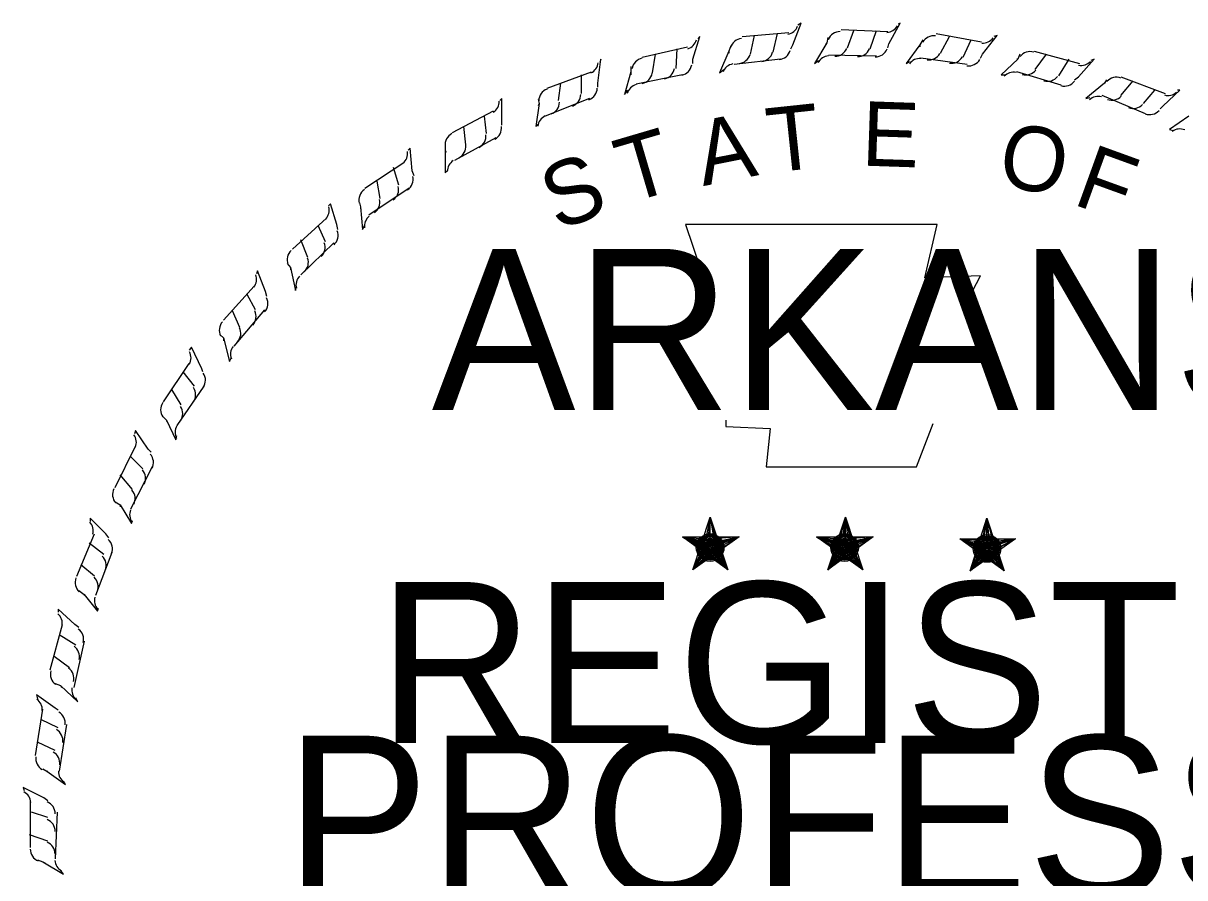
# Model space of a CAD drawing. Extents: x 1369528 to 1373075, y 373809 to 376031.
# Drawn here: x 1372616.5 to 1372751.6, y 374052.1 to 374151.6 of the extents above; entities that cross this region are included whole.
import ezdxf

# ---------------------------------------------------------------- set-up
doc = ezdxf.new("R2010")
doc.units = 0
doc.layers.add('R_Border Notes', color=7, linetype='Continuous')

msp = doc.modelspace()

# ---------------------------------------------------------------- linework, layer by layer
at = {"layer": 'R_Border Notes'}
for p, q in [((1372706.03, 374149.04), (1372706.99, 374151.56)), ((1372706.99, 374151.56), (1372706.63, 374151.32)), ((1372717.19, 374149.16), (1372718.51, 374151.56)), ((1372718.51, 374151.56), (1372718.27, 374151.44)), ((1372700.15, 374150), (1372705.55, 374150.48)), ((1372701.11, 374147.96), (1372701.59, 374150.12)), ((1372703.75, 374148.2), (1372704.23, 374150.36)), ((1372711.67, 374150.84), (1372717.07, 374150.6)), ((1372712.39, 374148.68), (1372713.11, 374150.72)), ((1372715.03, 374148.56), (1372715.75, 374150.72)), ((1372722.71, 374150.36), (1372727.99, 374149.4)), ((1372728.11, 374147.96), (1372729.79, 374150.12)), ((1372729.79, 374150.12), (1372729.43, 374150)), ((1372688.51, 374147.6), (1372693.79, 374148.8)), ((1372694.39, 374147.36), (1372695.23, 374150)), ((1372695.23, 374150), (1372694.99, 374149.76)), ((1372698.83, 374148.92), (1372698.59, 374148.32)), ((1372705.79, 374148.56), (1372706.03, 374149.04)), ((1372709.99, 374149.28), (1372708.55, 374146.88)), ((1372709.99, 374149.28), (1372709.87, 374149.16)), ((1372710.11, 374149.88), (1372709.99, 374149.28)), ((1372717.07, 374148.68), (1372717.19, 374149.16)), ((1372720.79, 374149.04), (1372719.23, 374146.88)), ((1372721.15, 374149.64), (1372720.79, 374149.04)), ((1372720.79, 374149.04), (1372720.79, 374148.8)), ((1372723.19, 374148.08), (1372724.27, 374150)), ((1372725.83, 374147.6), (1372726.79, 374149.64)), ((1372683.35, 374144.6), (1372683.71, 374147.36)), ((1372683.71, 374147.36), (1372683.59, 374147)), ((1372689.71, 374145.8), (1372690.07, 374147.96)), ((1372692.47, 374146.28), (1372692.59, 374148.56)), ((1372694.39, 374146.88), (1372694.39, 374147.36)), ((1372698.59, 374148.32), (1372697.51, 374145.8)), ((1372698.59, 374148.32), (1372698.59, 374148.08)), ((1372704.59, 374147.36), (1372699.19, 374146.76)), ((1372715.75, 374147.72), (1372710.23, 374147.84)), ((1372726.31, 374146.76), (1372720.91, 374147.48)), ((1372727.87, 374147.48), (1372728.11, 374147.96)), ((1372732.19, 374147.36), (1372730.27, 374145.56)), ((1372732.19, 374147.36), (1372732.07, 374147.36)), ((1372732.43, 374147.96), (1372732.19, 374147.36)), ((1372734.11, 374148.32), (1372739.39, 374146.88)), ((1372734.23, 374146.16), (1372735.55, 374147.96)), ((1372736.99, 374145.44), (1372738.19, 374147.36)), ((1372739.27, 374145.32), (1372741.07, 374147.36)), ((1372741.07, 374147.36), (1372740.71, 374147.24)), ((1372687.19, 374146.52), (1372687.19, 374145.92)), ((1372697.51, 374145.8), (1372697.99, 374146.16)), ((1372708.55, 374146.88), (1372709.03, 374147.24)), ((1372719.23, 374146.88), (1372719.59, 374147.12)), ((1372677.47, 374144), (1372682.63, 374145.92)), ((1372681.43, 374143.4), (1372681.43, 374145.56)), ((1372687.19, 374145.92), (1372686.47, 374143.28)), ((1372687.19, 374145.92), (1372687.19, 374145.56)), ((1372693.19, 374145.56), (1372687.79, 374144.48)), ((1372730.27, 374145.56), (1372730.75, 374145.56)), ((1372737.23, 374144.36), (1372732.07, 374145.92)), ((1372738.79, 374144.96), (1372739.27, 374145.32)), ((1372742.51, 374144.96), (1372742.27, 374144.6)), ((1372744.19, 374145.32), (1372749.35, 374143.4)), ((1372744.19, 374143.16), (1372745.63, 374144.84)), ((1372678.79, 374142.56), (1372679.03, 374144.6)), ((1372683.35, 374144.12), (1372683.35, 374144.6)), ((1372686.47, 374143.28), (1372686.83, 374143.76)), ((1372742.27, 374144.6), (1372740.11, 374142.8)), ((1372742.27, 374144.6), (1372742.03, 374144.36)), ((1372746.83, 374142.2), (1372748.15, 374143.76)), ((1372749.11, 374141.96), (1372751.03, 374143.76)), ((1372751.03, 374143.76), (1372750.79, 374143.76)), ((1372672.19, 374142.8), (1372671.95, 374142.56)), ((1372672.19, 374140.16), (1372672.19, 374142.8)), ((1372676.51, 374142.2), (1372676.15, 374139.56)), ((1372676.39, 374142.68), (1372676.51, 374142.2)), ((1372676.51, 374142.2), (1372676.39, 374141.96)), ((1372682.39, 374142.8), (1372677.23, 374140.76)), ((1372740.11, 374142.8), (1372740.59, 374142.92)), ((1372747.07, 374141), (1372742.03, 374143.16)), ((1372748.75, 374141.6), (1372749.11, 374141.96)), ((1372666.43, 374138.84), (1372671.23, 374141.36)), ((1372670.39, 374138.72), (1372670.15, 374140.76)), ((1372752.11, 374140.76), (1372749.83, 374139.2)), ((1372667.99, 374137.4), (1372667.75, 374139.56)), ((1372672.19, 374139.68), (1372672.19, 374140.16)), ((1372676.15, 374139.56), (1372676.39, 374139.8)), ((1372671.47, 374138.24), (1372666.67, 374135.6)), ((1372749.83, 374139.2), (1372750.31, 374139.08)), ((1372661.51, 374137.04), (1372661.27, 374136.8)), ((1372661.75, 374134.4), (1372661.51, 374137.04)), ((1372665.59, 374137.4), (1372665.59, 374136.8)), ((1372665.59, 374136.8), (1372665.59, 374134.16)), ((1372665.59, 374136.8), (1372665.71, 374136.56)), ((1372656.23, 374132.36), (1372660.79, 374135.36)), ((1372660.19, 374132.72), (1372659.59, 374134.76)), ((1372661.99, 374133.8), (1372661.75, 374134.4)), ((1372665.59, 374134.16), (1372665.83, 374134.4)), ((1372658.03, 374131.16), (1372657.67, 374133.2)), ((1372661.39, 374132.36), (1372656.71, 374129.24)), ((1372652.27, 374130.56), (1372652.03, 374130.32)), ((1372652.99, 374128.16), (1372652.27, 374130.56)), ((1372655.63, 374130.68), (1372655.75, 374130.2)), ((1372655.75, 374130.2), (1372655.99, 374127.56)), ((1372655.75, 374130.2), (1372655.75, 374129.96)), ((1372647.83, 374125.28), (1372651.79, 374128.88)), ((1372651.67, 374126.12), (1372650.83, 374128.04)), ((1372653.11, 374127.56), (1372652.99, 374128.16)), ((1372655.99, 374127.56), (1372656.23, 374128.04)), ((1372649.63, 374124.32), (1372648.79, 374126.36)), ((1372652.63, 374126), (1372648.79, 374122.28)), ((1372647.23, 374123.6), (1372647.59, 374123.12)), ((1372647.59, 374123.12), (1372648.19, 374120.48)), ((1372647.59, 374123.12), (1372647.59, 374122.88)), ((1372643.75, 374122.76), (1372643.63, 374122.4)), ((1372644.71, 374120.36), (1372643.75, 374122.76)), ((1372639.79, 374117), (1372643.39, 374120.96)), ((1372644.83, 374119.76), (1372644.71, 374120.36)), ((1372648.19, 374120.48), (1372648.31, 374120.96)), ((1372643.51, 374118.2), (1372642.55, 374120)), ((1372641.71, 374116.16), (1372640.87, 374118.08)), ((1372644.59, 374118.2), (1372640.99, 374114)), ((1372639.43, 374115.32), (1372639.79, 374114.96)), ((1372639.79, 374114.96), (1372640.51, 374112.2)), ((1372639.79, 374114.96), (1372639.79, 374114.6)), ((1372636.07, 374113.88), (1372635.83, 374113.52)), ((1372637.27, 374111.36), (1372636.07, 374113.88)), ((1372640.51, 374112.2), (1372640.75, 374112.68)), ((1372632.83, 374107.52), (1372635.83, 374111.96)), ((1372636.43, 374109.32), (1372635.11, 374111)), ((1372637.39, 374111), (1372637.27, 374111.36)), ((1372634.87, 374107.16), (1372633.79, 374108.96)), ((1372637.51, 374109.32), (1372634.39, 374104.76)), ((1372632.71, 374105.84), (1372633.19, 374105.36)), ((1372629.59, 374104.16), (1372629.47, 374103.8)), ((1372631.03, 374102), (1372629.59, 374104.16)), ((1372633.19, 374105.36), (1372634.27, 374103.08)), ((1372633.19, 374105.36), (1372633.19, 374105.24)), ((1372634.27, 374103.08), (1372634.39, 374103.56)), ((1372627.19, 374097.56), (1372629.59, 374102.36)), ((1372631.39, 374101.64), (1372631.03, 374102)), ((1372630.43, 374099.72), (1372628.99, 374101.16)), ((1372629.23, 374097.32), (1372627.79, 374099)), ((1372631.51, 374099.96), (1372628.99, 374095.04)), ((1372627.19, 374095.88), (1372627.79, 374095.52)), ((1372627.79, 374095.52), (1372629.11, 374093.36)), ((1372627.79, 374095.52), (1372627.79, 374095.28)), ((1372626.11, 374092.16), (1372624.31, 374093.96)), ((1372624.31, 374093.96), (1372624.31, 374093.6)), ((1372629.11, 374093.36), (1372629.23, 374093.72)), ((1372696.43, 374094.08), (1372695.95, 374091.8)), ((1372696.43, 374094.08), (1372696.19, 374091.8)), ((1372696.43, 374094.08), (1372696.31, 374091.8)), ((1372696.43, 374090.72), (1372696.43, 374094.08)), ((1372696.43, 374094.08), (1372697.03, 374091.8)), ((1372696.43, 374094.08), (1372696.91, 374091.8)), ((1372696.43, 374094.08), (1372696.79, 374091.8)), ((1372712.15, 374094.08), (1372711.55, 374091.8)), ((1372712.15, 374094.08), (1372711.79, 374091.8)), ((1372712.15, 374094.08), (1372711.91, 374091.8)), ((1372712.15, 374090.72), (1372712.15, 374094.08)), ((1372712.15, 374094.08), (1372712.75, 374091.8)), ((1372712.15, 374094.08), (1372712.63, 374091.8)), ((1372712.15, 374094.08), (1372712.39, 374091.8)), ((1372728.59, 374093.96), (1372728.11, 374091.68)), ((1372728.59, 374093.96), (1372728.23, 374091.68)), ((1372728.59, 374090.6), (1372728.59, 374093.96)), ((1372728.59, 374093.96), (1372729.31, 374091.68)), ((1372728.59, 374093.96), (1372729.19, 374091.68)), ((1372728.59, 374093.96), (1372728.83, 374091.68)), ((1372728.59, 374093.96), (1372728.59, 374091.68)), ((1372622.75, 374087.24), (1372624.79, 374092.16)), ((1372626.47, 374091.68), (1372626.11, 374092.16)), ((1372625.87, 374089.76), (1372624.19, 374091.08)), ((1372693.19, 374091.8), (1372696.43, 374090.72)), ((1372693.19, 374091.8), (1372695.59, 374091.56)), ((1372693.19, 374091.8), (1372695.59, 374091.32)), ((1372693.19, 374091.8), (1372695.59, 374091.2)), ((1372693.19, 374091.8), (1372695.47, 374090.84)), ((1372693.19, 374091.8), (1372695.47, 374090.6)), ((1372693.19, 374091.8), (1372695.47, 374090.36)), ((1372694.39, 374087.96), (1372696.43, 374090.72)), ((1372699.79, 374091.8), (1372696.43, 374090.72)), ((1372698.47, 374087.96), (1372696.43, 374090.72)), ((1372699.79, 374091.8), (1372696.79, 374091.56)), ((1372699.79, 374091.8), (1372697.03, 374091.2)), ((1372699.79, 374091.8), (1372697.03, 374091.08)), ((1372698.47, 374087.96), (1372697.15, 374090.6)), ((1372698.47, 374087.96), (1372697.39, 374090.6)), ((1372699.79, 374091.8), (1372697.63, 374090.96)), ((1372699.79, 374091.8), (1372697.87, 374090.84)), ((1372699.79, 374091.8), (1372697.99, 374090.6)), ((1372708.79, 374091.8), (1372712.15, 374090.72)), ((1372708.79, 374091.8), (1372711.19, 374091.56)), ((1372708.79, 374091.8), (1372711.19, 374091.32)), ((1372708.79, 374091.8), (1372711.19, 374091.2)), ((1372708.79, 374091.8), (1372711.19, 374090.84)), ((1372708.79, 374091.8), (1372711.07, 374090.6)), ((1372708.79, 374091.8), (1372711.07, 374090.36)), ((1372710.11, 374087.96), (1372712.15, 374090.72)), ((1372715.39, 374091.8), (1372712.15, 374090.72)), ((1372714.19, 374087.96), (1372712.15, 374090.72)), ((1372715.39, 374091.8), (1372712.51, 374091.56)), ((1372715.39, 374091.8), (1372712.63, 374091.2)), ((1372715.39, 374091.8), (1372712.63, 374091.08)), ((1372714.19, 374087.96), (1372712.87, 374090.6)), ((1372714.19, 374087.96), (1372712.99, 374090.6)), ((1372715.39, 374091.8), (1372713.23, 374090.96)), ((1372715.39, 374091.8), (1372713.47, 374090.84)), ((1372715.39, 374091.8), (1372713.59, 374090.6)), ((1372725.47, 374091.56), (1372728.59, 374090.6)), ((1372725.47, 374091.56), (1372727.87, 374091.44)), ((1372725.47, 374091.56), (1372727.87, 374091.2)), ((1372725.47, 374091.56), (1372727.63, 374090.96)), ((1372725.47, 374091.56), (1372727.63, 374090.72)), ((1372725.47, 374091.56), (1372727.63, 374090.48)), ((1372725.47, 374091.56), (1372727.63, 374090.36)), ((1372726.67, 374087.84), (1372728.59, 374090.6)), ((1372731.95, 374091.56), (1372728.59, 374090.6)), ((1372730.63, 374087.84), (1372728.59, 374090.6)), ((1372731.95, 374091.56), (1372729.07, 374091.44)), ((1372731.95, 374091.56), (1372729.19, 374091.2)), ((1372731.95, 374091.56), (1372729.19, 374090.96)), ((1372730.63, 374087.84), (1372729.67, 374090.6)), ((1372731.95, 374091.56), (1372729.79, 374090.84)), ((1372731.95, 374091.56), (1372730.03, 374090.6)), ((1372731.95, 374091.56), (1372730.15, 374090.6)), ((1372626.83, 374090), (1372624.91, 374084.96)), ((1372694.39, 374087.96), (1372695.59, 374090.48)), ((1372694.39, 374087.96), (1372695.59, 374090.24)), ((1372694.39, 374087.96), (1372695.83, 374090.12)), ((1372694.39, 374087.96), (1372696.43, 374090)), ((1372694.39, 374087.96), (1372696.19, 374089.88)), ((1372694.39, 374087.96), (1372696.43, 374089.76)), ((1372698.47, 374087.96), (1372696.43, 374089.88)), ((1372698.47, 374087.96), (1372696.43, 374089.76)), ((1372698.47, 374087.96), (1372696.79, 374089.88)), ((1372698.47, 374087.96), (1372697.03, 374090.24)), ((1372710.11, 374087.96), (1372711.19, 374090.48)), ((1372710.11, 374087.96), (1372711.19, 374090.24)), ((1372710.11, 374087.96), (1372711.43, 374090.12)), ((1372710.11, 374087.96), (1372712.03, 374090)), ((1372710.11, 374087.96), (1372711.79, 374089.88)), ((1372710.11, 374087.96), (1372712.15, 374089.76)), ((1372714.19, 374087.96), (1372712.03, 374089.88)), ((1372714.19, 374087.96), (1372712.03, 374089.76)), ((1372714.19, 374087.96), (1372712.39, 374089.88)), ((1372714.19, 374087.96), (1372712.75, 374090.24)), ((1372726.67, 374087.84), (1372727.63, 374090.36)), ((1372726.67, 374087.84), (1372727.87, 374090.12)), ((1372726.67, 374087.84), (1372727.99, 374090)), ((1372726.67, 374087.84), (1372728.23, 374089.76)), ((1372726.67, 374087.84), (1372728.59, 374089.76)), ((1372726.67, 374087.84), (1372728.71, 374089.64)), ((1372730.63, 374087.84), (1372728.59, 374089.76)), ((1372730.63, 374087.84), (1372728.59, 374089.52)), ((1372730.63, 374087.84), (1372729.07, 374089.76)), ((1372730.63, 374087.84), (1372729.31, 374090.12)), ((1372730.63, 374087.84), (1372729.43, 374090.48)), ((1372624.79, 374087.24), (1372623.23, 374088.56)), ((1372622.99, 374085.56), (1372623.59, 374085.08)), ((1372623.59, 374085.08), (1372625.15, 374083.16)), ((1372623.59, 374085.08), (1372623.59, 374084.96)), ((1372622.51, 374081.6), (1372620.59, 374083.4)), ((1372620.59, 374083.4), (1372620.59, 374083.04)), ((1372625.15, 374083.16), (1372625.27, 374083.52)), ((1372619.63, 374076.32), (1372621.07, 374081.6)), ((1372622.99, 374081.24), (1372622.51, 374081.6)), ((1372622.63, 374079.2), (1372620.71, 374080.4)), ((1372623.59, 374079.68), (1372622.39, 374074.28)), ((1372621.91, 374076.56), (1372620.11, 374077.88)), ((1372620.23, 374074.76), (1372620.83, 374074.52)), ((1372620.83, 374074.52), (1372622.87, 374072.6)), ((1372620.83, 374074.52), (1372620.95, 374074.28)), ((1372620.23, 374071.88), (1372618.07, 374073.44)), ((1372618.07, 374073.44), (1372618.19, 374072.96)), ((1372622.87, 374072.6), (1372622.63, 374073.08)), ((1372617.95, 374066.36), (1372618.79, 374071.76)), ((1372620.59, 374071.64), (1372620.23, 374071.88)), ((1372620.59, 374069.6), (1372618.55, 374070.56)), ((1372621.55, 374069.96), (1372620.71, 374064.56)), ((1372620.23, 374066.96), (1372618.19, 374067.92)), ((1372618.79, 374064.8), (1372619.27, 374064.56)), ((1372619.27, 374064.56), (1372621.43, 374063)), ((1372619.27, 374064.56), (1372619.39, 374064.56)), ((1372618.91, 374061.44), (1372616.51, 374062.64)), ((1372616.51, 374062.64), (1372616.63, 374062.28)), ((1372621.43, 374063), (1372621.19, 374063.36)), ((1372617.35, 374055.68), (1372617.35, 374061.08)), ((1372619.39, 374061.08), (1372618.91, 374061.44)), ((1372619.39, 374059.16), (1372617.47, 374059.76)), ((1372620.47, 374059.76), (1372620.23, 374054.36)), ((1372619.39, 374056.4), (1372617.23, 374057.12)), ((1372618.19, 374054.24), (1372618.79, 374054)), ((1372618.79, 374054), (1372621.19, 374052.56)), ((1372618.79, 374054), (1372619.03, 374053.88)), ((1372621.19, 374052.56), (1372620.83, 374053.04))]:
    msp.add_line(p, q, dxfattribs=at)
for points in [[(1372693.55, 374128.16), (1372696.19, 374120.36)], [(1372726.43, 374119.4), (1372727.87, 374122.16), (1372721.39, 374121.92), (1372722.83, 374128.16), (1372693.55, 374128.16)], [(1372698.23, 374105.36), (1372698.23, 374104.64), (1372703.39, 374104.4), (1372702.91, 374099.96), (1372720.43, 374099.96), (1372722.35, 374105)], [(1372696.43, 374094.08), (1372698.47, 374087.96), (1372693.19, 374091.8), (1372699.79, 374091.8), (1372694.39, 374087.96), (1372696.43, 374094.08)], [(1372712.15, 374094.08), (1372714.19, 374087.96), (1372708.79, 374091.8), (1372715.39, 374091.8), (1372710.11, 374087.96), (1372712.15, 374094.08)], [(1372728.59, 374093.96), (1372730.63, 374087.84), (1372725.47, 374091.56), (1372731.95, 374091.56), (1372726.67, 374087.84), (1372728.59, 374093.96)]]:
    msp.add_lwpolyline(points, dxfattribs=at)
for centre, radius in [((1372696.41, 374090.56), 1.61), ((1372696.41, 374090.56), 1.46), ((1372696.41, 374090.56), 1.36), ((1372712.05, 374090.56), 1.61), ((1372712.05, 374090.56), 1.46), ((1372712.05, 374090.56), 1.36), ((1372728.62, 374090.45), 1.61), ((1372728.62, 374090.45), 1.46), ((1372696.41, 374090.56), 1.24), ((1372696.41, 374090.56), 1.09), ((1372696.41, 374090.56), 1.01), ((1372696.41, 374090.56), 0.929), ((1372696.41, 374090.56), 0.8), ((1372696.41, 374090.56), 0.701), ((1372696.41, 374090.56), 0.583), ((1372696.41, 374090.56), 0.464), ((1372696.41, 374090.56), 0.346), ((1372696.41, 374090.56), 0.278), ((1372696.41, 374090.56), 0.135), ((1372712.05, 374090.56), 1.24), ((1372712.05, 374090.56), 1.09), ((1372712.05, 374090.56), 1.01), ((1372712.05, 374090.56), 0.929), ((1372712.05, 374090.56), 0.8), ((1372712.05, 374090.56), 0.701), ((1372712.05, 374090.56), 0.583), ((1372712.05, 374090.56), 0.464), ((1372712.05, 374090.56), 0.346), ((1372712.05, 374090.56), 0.278), ((1372712.05, 374090.56), 0.135), ((1372728.62, 374090.45), 1.36), ((1372728.62, 374090.45), 1.24), ((1372728.62, 374090.45), 1.09), ((1372728.62, 374090.45), 1.01), ((1372728.62, 374090.45), 0.929), ((1372728.62, 374090.45), 0.8), ((1372728.62, 374090.45), 0.701), ((1372728.62, 374090.45), 0.583), ((1372728.62, 374090.45), 0.464), ((1372728.62, 374090.45), 0.346), ((1372728.62, 374090.45), 0.278), ((1372728.62, 374090.45), 0.135)]:
    msp.add_circle(centre, radius, dxfattribs=at)
for centre, start, end in [((1372705.21, 374151.75), 279.9249, 338.7128), ((1372711.51, 374149.1), 89.1628, 157.5368), ((1372716.88, 374151.96), 273.4236, 332.2115), ((1372722.41, 374148.61), 81.4231, 149.797), ((1372693.39, 374150.01), 286.2701, 345.0579), ((1372700.2, 374148.31), 95.6641, 164.0381), ((1372728.12, 374150.72), 265.6839, 324.4717), ((1372688.79, 374146.03), 102.0093, 170.3832), ((1372699.63, 374148.34), 275.6641, 344.0381), ((1372702.26, 374148.59), 275.6641, 344.0381), ((1372704.3, 374148.8), 275.6641, 344.0381), ((1372710.27, 374146.27), 93.4236, 152.2115), ((1372710.94, 374149.2), 269.1628, 337.5368), ((1372713.58, 374149.15), 269.1628, 337.5368), ((1372715.64, 374149.13), 269.1628, 337.5368), ((1372720.8, 374145.98), 85.6839, 144.4717), ((1372721.86, 374148.78), 261.4231, 329.797), ((1372724.47, 374148.38), 261.4231, 329.797), ((1372726.5, 374148.08), 261.4231, 329.797), ((1372733.64, 374146.78), 73.9909, 142.3649), ((1372681.92, 374147.13), 294.8371, 353.6249), ((1372690.8, 374146.54), 282.0093, 350.3832), ((1372692.81, 374146.97), 282.0093, 350.3832), ((1372699.29, 374145.36), 99.9249, 158.7128), ((1372733.12, 374147.02), 253.9909, 322.3649), ((1372739.57, 374148.13), 258.2517, 317.0395), ((1372688.21, 374146), 282.0093, 350.3832), ((1372731.7, 374144.38), 78.2517, 137.0395), ((1372735.65, 374146.28), 253.9909, 322.3649), ((1372737.63, 374145.72), 253.9909, 322.3649), ((1372743.66, 374143.79), 69.0955, 137.4695), ((1372677.96, 374142.51), 110.5763, 178.9503), ((1372679.88, 374143.31), 290.5763, 358.9503), ((1372681.8, 374144.04), 290.5763, 358.9503), ((1372688.21, 374143), 106.2701, 165.0579), ((1372749.68, 374144.63), 253.3563, 312.1441), ((1372670.41, 374142.47), 301.9545, 0.7423), ((1372677.4, 374142.39), 290.5763, 358.9503), ((1372741.52, 374141.56), 73.3563, 132.1441), ((1372743.15, 374144.08), 249.0955, 317.4695), ((1372745.62, 374143.12), 249.0955, 317.4695), ((1372677.84, 374139.43), 114.8371, 173.6249), ((1372747.54, 374142.4), 249.0955, 317.4695), ((1372670.67, 374139.39), 297.6937, 6.0677), ((1372751.04, 374137.78), 67.3316, 126.1194), ((1372667.06, 374137.4), 117.6937, 186.0677), ((1372668.86, 374138.43), 297.6937, 6.0677), ((1372659.74, 374136.42), 309.1135, 7.9014), ((1372666.51, 374137.21), 297.6937, 6.0677), ((1372667.32, 374134.32), 121.9545, 180.7423), ((1372658.7, 374132.22), 304.8528, 13.2267), ((1372660.38, 374133.4), 304.8528, 13.2267), ((1372657.04, 374130.98), 124.8528, 193.2267), ((1372650.62, 374129.79), 316.8235, 15.6113), ((1372656.52, 374130.72), 304.8528, 13.2267), ((1372657.68, 374127.95), 129.1135, 187.9014), ((1372651.66, 374126.88), 312.5627, 20.9367), ((1372650.15, 374125.49), 312.5627, 20.9367), ((1372648.68, 374124.03), 132.5627, 200.9367), ((1372648.2, 374123.71), 312.5627, 20.9367), ((1372642.17, 374121.76), 322.2653, 21.0531), ((1372649.72, 374121.12), 136.8235, 195.6113), ((1372643.49, 374118.96), 318.0045, 26.3785), ((1372642.12, 374117.43), 318.0045, 26.3785), ((1372640.79, 374115.84), 138.0045, 206.3785), ((1372640.34, 374115.48), 318.0045, 26.3785), ((1372642.1, 374113.05), 142.2653, 201.0531), ((1372634.55, 374112.63), 329.9636, 28.7515), ((1372636.23, 374110.03), 325.7028, 34.0768), ((1372635.08, 374108.33), 325.7028, 34.0768), ((1372633.97, 374106.58), 145.7028, 214.0768), ((1372633.58, 374106.15), 325.7028, 34.0768), ((1372635.65, 374103.98), 149.9636, 208.7515), ((1372628.19, 374102.81), 337.2243, 36.0121), ((1372630.18, 374100.45), 332.9635, 41.3375), ((1372629.26, 374098.61), 332.9635, 41.3375), ((1372628.38, 374096.73), 152.9635, 221.3375), ((1372628.05, 374096.26), 332.9635, 41.3375), ((1372630.37, 374094.37), 157.2243, 216.0121), ((1372623.17, 374092.52), 343.6465, 42.4343), ((1372625.41, 374090.39), 339.3857, 47.7597), ((1372624.69, 374088.47), 339.3857, 47.7597), ((1372624.03, 374086.5), 159.3857, 227.7597), ((1372623.75, 374086), 339.3857, 47.7597), ((1372626.28, 374084.37), 163.6465, 222.4343), ((1372619.58, 374081.72), 350.445, 49.2329), ((1372622.06, 374079.87), 346.1842, 54.5582), ((1372621.57, 374077.88), 346.1842, 54.5582), ((1372621.15, 374075.85), 166.1842, 234.5582), ((1372620.93, 374075.31), 346.1842, 54.5582), ((1372623.63, 374074), 170.445, 229.2329), ((1372617.25, 374071.69), 356.646, 55.4338), ((1372619.92, 374070.12), 352.3852, 60.7592), ((1372619.65, 374068.08), 352.3852, 60.7592), ((1372619.29, 374065.47), 352.3852, 60.7592), ((1372619.45, 374066.02), 172.3852, 240.7592), ((1372622.11, 374064.45), 176.646, 235.4338), ((1372615.91, 374060.81), 3.9474, 62.7352), ((1372618.75, 374059.6), 359.6866, 68.0606), ((1372618.75, 374057.54), 359.6866, 68.0606), ((1372618.81, 374055.47), 179.6866, 248.0606), ((1372618.73, 374054.9), 359.6866, 68.0606), ((1372621.66, 374054.26), 183.9474, 242.7352)]:
    msp.add_arc(centre, 1.48, start, end, dxfattribs=at)

# ---------------------------------------------------------------- texts
for s, rotation, p in [('T', 6.0228, (1372703.39, 374134.16)), ('E', 358.0732, (1372713.95, 374135)), ('A', 11.2132, (1372695.59, 374132.6)), ('T', 16.4036, (1372686.83, 374130.56)), ('O', 350.4515, (1372729.67, 374132.72)), ('F', 340.0707, (1372738.43, 374130.56)), ('S', 21.594, (1372678.67, 374127.32))]:
    msp.add_text(s, height=7.5, rotation=rotation, dxfattribs=at).set_placement(p)
for s, height, p in [('ARKANSAS', 18.749, (1372664.03, 374106.56)), ('REGISTERED', 18.749, (1372657.79, 374067.8)), ('PROFESSIONAL', 18.7488, (1372646.99, 374049.92))]:
    msp.add_text(s, height=height, dxfattribs=at).set_placement(p)

doc.saveas('drawing.dxf')
